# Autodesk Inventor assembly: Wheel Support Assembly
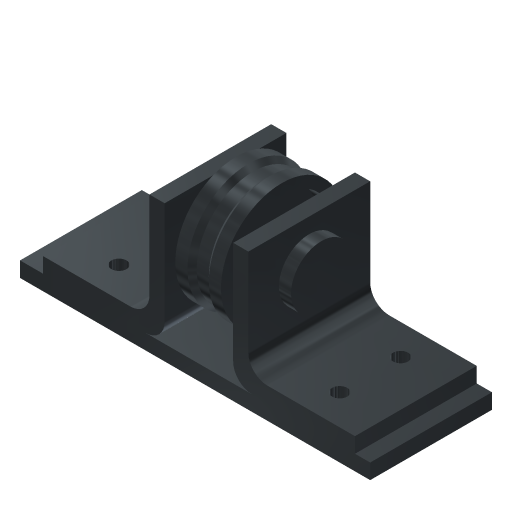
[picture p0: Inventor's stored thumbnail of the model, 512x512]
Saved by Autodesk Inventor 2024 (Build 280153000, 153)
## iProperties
Created: 2016-08
Part Number: Wheel Support Assembly
Document SubType Name: Assembly
Designer: Sandeep
Author: Sandeep
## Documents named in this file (5)
- D:\PROJECTS\Project 2023\RESOURCES INVENTOR 2024\RESOURCES INVENTOR 2024\Inventor_2024_tut\Inventor_2024_tut\c15_Inv_2024_tut\c15_Inv_tut_2024\c15_tut03_inv\Wheel Support Assembly.iam
- D:\PROJECTS\Project 2023\RESOURCES INVENTOR 2024\RESOURCES INVENTOR 2024\Inventor_2024_tut\Inventor_2024_tut\c15_Inv_2024_tut\c15_Inv_tut_2024\c15_tut03_inv\base.ipt
- D:\PROJECTS\Project 2023\RESOURCES INVENTOR 2024\RESOURCES INVENTOR 2024\Inventor_2024_tut\Inventor_2024_tut\c15_Inv_2024_tut\c15_Inv_tut_2024\c15_tut03_inv\Support.ipt
- D:\PROJECTS\Project 2023\RESOURCES INVENTOR 2024\RESOURCES INVENTOR 2024\Inventor_2024_tut\Inventor_2024_tut\c15_Inv_2024_tut\c15_Inv_tut_2024\c15_tut03_inv\Wheel.ipt
- D:\PROJECTS\Project 2023\RESOURCES INVENTOR 2024\RESOURCES INVENTOR 2024\Inventor_2024_tut\Inventor_2024_tut\c15_Inv_2024_tut\c15_Inv_tut_2024\c15_tut03_inv\Shoulder screw.ipt
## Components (5 placed, 4 different names)
1. base:1 — Insert:1, Mate:1, Insert:2, Mate:2
2. Support:1 — Insert:1, Mate:1, Insert:3
3. Support:2 — Insert:2, Mate:2, Mate:3, Mate:4
4. Wheel:1 — Insert:3
5. Shoulder screw:1 — Mate:3, Mate:4
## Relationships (7: Mate 4, Insert 3)
- Insert:1: base:1 ↔ Support:1
- Mate:1: base:1 ↔ Support:1
- Insert:2: base:1 ↔ Support:2
- Mate:2: base:1 ↔ Support:2
- Insert:3: Support:1 ↔ Wheel:1
- Mate:3: Support:2 ↔ Shoulder screw:1
- Mate:4: Support:2 ↔ Shoulder screw:1
